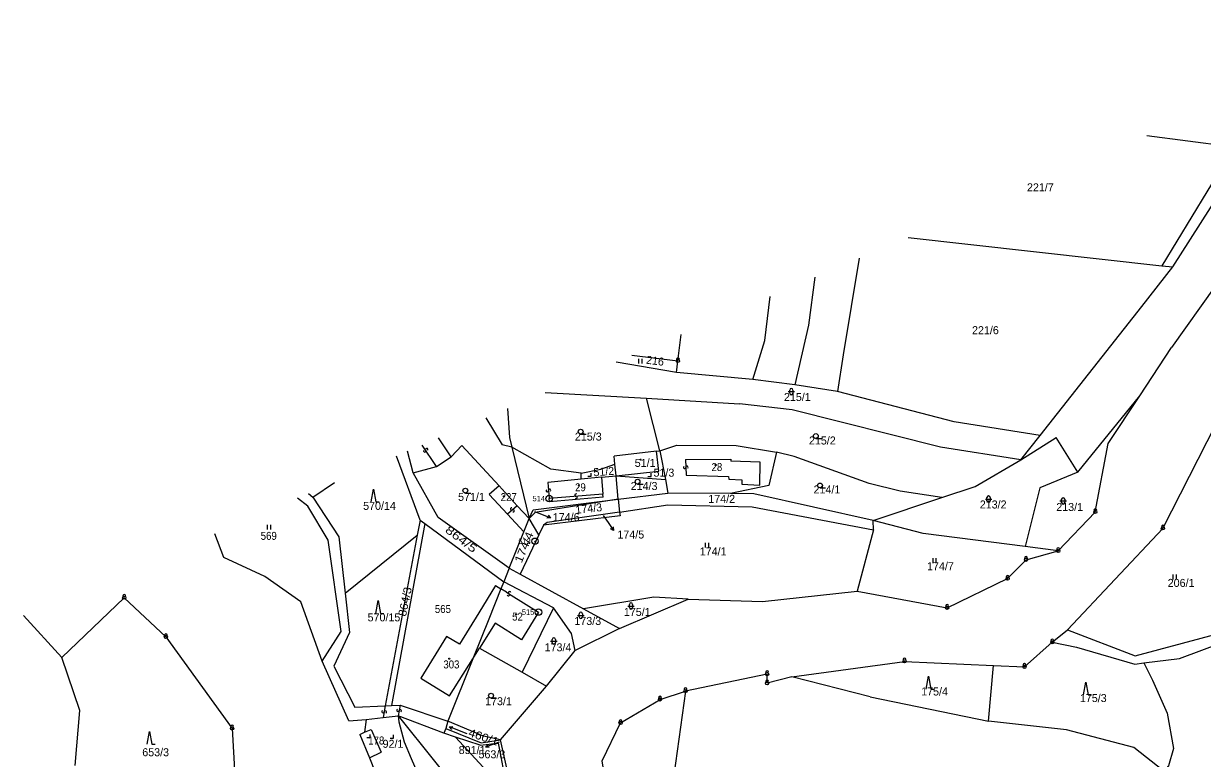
# Model space of a CAD drawing. Extents: x -680102 to -677253, y -1007548 to -1006096.
# Drawn here: x -679151.4 to -678783.2, y -1006742.4 to -1006513 of the extents above; entities that cross this region are included whole.
import ezdxf
from ezdxf.enums import TextEntityAlignment as Align

# ---------------------------------------------------------------- set-up
doc = ezdxf.new("R2010")
doc.units = 0
for name, color, linetype, lineweight in [('1', 7, 'Continuous', 25), ('13', 7, 'Continuous', 25), ('16', 7, 'Continuous', 25), ('24', 7, 'Continuous', 25), ('25', 7, 'Continuous', 25), ('4', 7, 'Continuous', 25)]:
    doc.layers.add(name, color=color, linetype=linetype, lineweight=lineweight)
for name, color, linetype in [('17', 7, 'Continuous'), ('18', 7, 'Continuous'), ('19', 7, 'Continuous')]:
    doc.layers.add(name, color=color, linetype=linetype)

msp = doc.modelspace()

# ---------------------------------------------------------------- linework, layer by layer
at = {"layer": '1'}
for p, q in [((-678800.53, -1006547.85), (-678772.56, -1006551.5)), ((-678875.09, -1006579.69), (-678795.83, -1006588.55)), ((-678890.35, -1006586.21), (-678895.4, -1006616.36)), ((-678904.28, -1006592.16), (-678906.23, -1006607.1)), ((-678906.23, -1006607.1), (-678910.46, -1006625.75)), ((-678947.49, -1006621.84), (-678966.26, -1006618.63)), ((-678895.4, -1006616.36), (-678897.14, -1006627.84)), ((-678988.49, -1006628.13), (-678956.82, -1006629.92)), ((-678822.11, -1006653.04), (-678802.77, -1006629.14)), ((-678952.68, -1006646.32), (-678956.82, -1006629.92)), ((-678956.82, -1006629.92), (-678927.82, -1006631.69)), ((-678911.3, -1006633.54), (-678927.82, -1006631.69)), ((-679006.99, -1006636.03), (-679001.94, -1006644.48)), ((-679017.85, -1006648.21), (-679021.74, -1006642.33)), ((-678998.89, -1006645.23), (-679001.94, -1006644.48)), ((-678839.88, -1006649.19), (-678828.9, -1006642.14)), ((-678822.11, -1006653.04), (-678828.9, -1006642.14)), ((-679027.56, -1006667.94), (-679034.94, -1006647.97)), ((-679029.72, -1006653.21), (-679031.49, -1006646.49)), ((-679002.88, -1006657.31), (-679014.55, -1006644.71)), ((-678986.72, -1006652.08), (-678998.89, -1006645.23)), ((-678952.68, -1006646.32), (-678947.3, -1006644.57)), ((-678916.24, -1006646.74), (-678918.62, -1006657.2)), ((-679029.72, -1006653.21), (-679022.42, -1006651.27)), ((-678971.11, -1006652.1), (-678966.67, -1006650.52)), ((-678977.27, -1006653.32), (-678971.11, -1006652.1)), ((-678970.91, -1006654.6), (-678977.24, -1006655.21)), ((-678970.91, -1006654.6), (-678966.28, -1006654.13)), ((-678966.28, -1006654.13), (-678953, -1006652.65)), ((-678965.7, -1006661.44), (-678966.28, -1006654.13)), ((-678966.28, -1006654.13), (-678950.89, -1006655.33)), ((-678822.11, -1006653.04), (-678833.99, -1006657.87)), ((-679061.04, -1006660.76), (-679054.28, -1006656.23)), ((-679002.88, -1006657.31), (-679005.93, -1006659.95)), ((-678918.62, -1006657.2), (-678930.63, -1006659.69)), ((-678864.57, -1006660.95), (-678877.56, -1006658.92)), ((-678833.99, -1006657.87), (-678838.55, -1006676.25)), ((-679062.63, -1006663.61), (-679065.81, -1006661.15)), ((-679062.41, -1006659.7), (-679061.04, -1006660.76)), ((-679061.04, -1006660.76), (-679052.88, -1006673.15)), ((-679000.23, -1006666.1), (-679005.93, -1006659.95)), ((-678965.7, -1006661.44), (-678991.57, -1006665.59)), ((-678965.7, -1006661.44), (-678950.19, -1006659.59)), ((-679056.21, -1006674.25), (-679062.63, -1006663.61)), ((-678995.13, -1006671.61), (-679000.23, -1006666.1)), ((-678991.57, -1006665.59), (-678993.47, -1006667.47)), ((-678965.21, -1006665.45), (-678950.17, -1006663.23)), ((-679026.09, -1006669.03), (-679036.42, -1006725.89)), ((-678990.43, -1006672.51), (-678993.47, -1006667.47)), ((-678965.06, -1006666.67), (-678989.01, -1006669.52)), ((-678870.38, -1006672.11), (-678885.98, -1006668.07)), ((-679050.96, -1006690.78), (-679028.44, -1006672.66)), ((-678885.94, -1006671.03), (-678890.99, -1006690.13)), ((-679003.94, -1006688.36), (-679002.28, -1006689.39)), ((-679139.41, -1006710.89), (-679119.95, -1006692.18)), ((-678954.49, -1006692.05), (-678976.49, -1006695.68)), ((-678985.89, -1006695.35), (-678995.64, -1006715.45)), ((-678976.49, -1006695.68), (-678965.27, -1006701.83)), ((-679151.39, -1006697.71), (-679139.41, -1006710.89)), ((-678965.27, -1006701.83), (-678979.06, -1006708.64)), ((-679011.06, -1006711.25), (-679008.94, -1006707.89)), ((-679133.78, -1006727.4), (-679139.41, -1006710.89)), ((-679018.38, -1006722.85), (-679011.06, -1006711.25)), ((-678911.38, -1006716.94), (-678876.22, -1006712.06)), ((-678849.98, -1006730.68), (-678848.47, -1006713.33)), ((-678886.94, -1006723.16), (-678911.38, -1006716.94)), ((-679002.4, -1006736.58), (-678988.1, -1006719.85)), ((-678886.94, -1006723.16), (-678849.98, -1006730.68)), ((-679135.24, -1006744.53), (-679133.78, -1006727.4)), ((-679047.91, -1006726.37), (-679038.41, -1006725.97)), ((-679033.77, -1006725.78), (-679018.9, -1006730.77)), ((-679046.38, -1006734.91), (-679044.89, -1006734.19)), ((-679046.38, -1006734.91), (-679043.31, -1006742.18)), ((-679044.89, -1006734.19), (-679042.83, -1006733.34)), ((-679042.83, -1006733.34), (-679039.71, -1006740.37)), ((-679019.52, -1006733.05), (-679020.07, -1006734.51)), ((-679005.39, -1006747.73), (-679016.43, -1006735.68)), ((-679043.31, -1006742.18), (-679039.71, -1006740.37)), ((-679043.31, -1006742.18), (-679035.43, -1006762.21)), ((-679002.29, -1006741.89), (-679001.73, -1006745.16))]:
    msp.add_line(p, q, dxfattribs=at)
for points in [[(-678718.85, -1006512.96), (-678727.87, -1006520.67), (-678750.9, -1006553.44), (-678779.15, -1006594.96), (-678792.87, -1006614.12)], [(-678833.83, -1006641.55), (-678802.15, -1006601.31), (-678792.37, -1006588.89), (-678778.26, -1006566.69), (-678751.77, -1006529.49), (-678748.59, -1006525.66)], [(-678777.09, -1006557.74), (-678795.83, -1006588.55), (-678792.37, -1006588.89)], [(-678923.64, -1006624.05), (-678919.88, -1006611.91), (-678918.24, -1006598.12)], [(-678828.22, -1006677.6), (-678816.63, -1006665.45), (-678812.58, -1006644.03), (-678802.77, -1006629.14), (-678792.87, -1006614.12)], [(-678839.88, -1006649.19), (-678833.83, -1006641.55), (-678860.72, -1006637.24), (-678897.14, -1006627.84), (-678910.46, -1006625.75), (-678923.64, -1006624.05), (-678947.49, -1006621.84), (-678946.99, -1006618.31)], [(-678825.3, -1006702.25), (-678795.52, -1006670.55), (-678770.69, -1006621.83), (-678771.83, -1006639.32), (-678780, -1006672.18), (-678768.75, -1006700.87)], [(-678854.19, -1006657.49), (-678839.88, -1006649.19), (-678865.03, -1006645.21), (-678911.3, -1006633.54)], [(-679022.42, -1006651.27), (-679017.85, -1006648.21), (-679014.55, -1006644.71)], [(-678953, -1006652.65), (-678953.69, -1006646.44), (-678966.94, -1006647.96)], [(-678966.28, -1006654.13), (-678966.67, -1006650.52), (-678966.94, -1006647.96)], [(-678953.69, -1006646.44), (-678952.68, -1006646.32), (-678950.89, -1006655.33), (-678950.19, -1006659.59)], [(-678947.3, -1006644.57), (-678928.77, -1006644.65), (-678916.24, -1006646.74)], [(-678877.56, -1006658.92), (-678887.22, -1006656.57), (-678910.72, -1006648.08), (-678916.24, -1006646.74)], [(-678999.7, -1006682.97), (-679021.88, -1006667.12), (-679029.72, -1006653.21)], [(-678977.24, -1006655.21), (-678977.27, -1006653.32), (-678986.72, -1006652.08)], [(-678993.47, -1006667.47), (-678997.18, -1006663.47), (-679002.88, -1006657.31)], [(-678885.98, -1006668.07), (-678864.57, -1006660.95), (-678854.19, -1006657.49)], [(-678993.47, -1006667.47), (-678992.27, -1006664.73), (-678965.7, -1006661.44)], [(-678965.7, -1006661.44), (-678965.21, -1006665.45), (-678965.06, -1006666.67)], [(-678923.28, -1006659.73), (-678930.63, -1006659.69), (-678950.19, -1006659.59)], [(-678885.94, -1006671.03), (-678885.98, -1006668.07), (-678923.28, -1006659.73)], [(-678965.21, -1006665.45), (-678987.83, -1006668.67), (-678989.01, -1006669.52)], [(-678950.17, -1006663.23), (-678923.81, -1006663.85), (-678885.94, -1006671.03)], [(-679027.56, -1006667.94), (-679028.44, -1006672.66), (-679038.41, -1006725.97)], [(-679027.56, -1006667.94), (-679026.09, -1006669.03), (-679001.42, -1006687.25)], [(-678989.01, -1006669.52), (-678990.43, -1006672.51), (-678996.3, -1006684.83)], [(-679049.77, -1006730.67), (-679058.14, -1006711.95), (-679064.82, -1006693.49), (-679076.06, -1006685.58), (-679088.89, -1006679.61), (-679091.68, -1006672.2)], [(-679052.88, -1006673.15), (-679050.96, -1006690.78), (-679049.63, -1006703.03)], [(-678828.22, -1006677.6), (-678838.55, -1006676.25), (-678870.38, -1006672.11)], [(-679058.14, -1006711.95), (-679052.24, -1006702.77), (-679056.21, -1006674.25)], [(-678943.78, -1006692.62), (-678920.62, -1006693.39), (-678890.99, -1006690.13), (-678862.92, -1006695.35), (-678844.01, -1006686.22), (-678838.27, -1006680.34), (-678828.22, -1006677.6)], [(-678999.7, -1006682.97), (-678996.3, -1006684.83), (-678976.49, -1006695.68)], [(-679003.94, -1006688.36), (-679009.2, -1006696.89), (-679015.28, -1006706.74), (-679019.25, -1006704.29), (-679027.31, -1006717.34), (-679018.38, -1006722.85)], [(-678980.21, -1006703.33), (-678985.89, -1006695.35), (-679001.42, -1006687.25)], [(-679119.95, -1006692.18), (-679106.93, -1006704.42), (-679086.25, -1006732.99)], [(-678965.27, -1006701.83), (-678943.78, -1006692.62), (-678954.49, -1006692.05)], [(-678830.07, -1006706.12), (-678825.3, -1006702.25), (-678804.17, -1006710.32), (-678768.75, -1006700.87), (-678759.35, -1006690.53)], [(-679049.63, -1006703.03), (-679054.45, -1006713.53), (-679047.91, -1006726.37)], [(-678988.1, -1006719.85), (-678979.06, -1006708.64), (-678980.21, -1006703.33)], [(-678801.5, -1006712.47), (-678790.35, -1006711.15), (-678764.08, -1006701.41)], [(-678838.75, -1006713.78), (-678830.07, -1006706.12), (-678822.48, -1006707.68), (-678804.29, -1006712.9), (-678801.5, -1006712.47), (-678798.75, -1006717.89)], [(-679008.94, -1006707.89), (-678995.64, -1006715.45), (-678988.1, -1006719.85)], [(-678876.22, -1006712.06), (-678848.47, -1006713.33), (-678838.75, -1006713.78)], [(-678911.38, -1006716.94), (-678919.14, -1006718.89), (-678919.14, -1006716.04), (-678944.63, -1006721.34)], [(-678798.75, -1006717.89), (-678794.19, -1006728.21), (-678792.25, -1006739.23), (-678793.8, -1006744.67), (-678795.23, -1006746.35), (-678804.55, -1006738.97), (-678825.66, -1006733.4), (-678849.98, -1006730.68)], [(-678972.03, -1006782.95), (-678974.11, -1006769.23), (-678969.55, -1006750.45), (-678970.65, -1006743.09), (-678964.92, -1006731.27), (-678952.59, -1006723.96), (-678944.63, -1006721.34)], [(-678944.63, -1006721.34), (-678954, -1006788.76), (-678925.55, -1006782.25), (-678911.96, -1006785.6), (-678905.55, -1006793.77), (-678908.87, -1006800.86), (-678918.43, -1006806.7), (-678921.1, -1006820.24)], [(-679044.33, -1006730.22), (-679039.1, -1006729.63), (-679034.41, -1006729.1)], [(-679038.41, -1006725.97), (-679036.42, -1006725.89), (-679033.77, -1006725.78)], [(-679020.07, -1006734.51), (-679034.41, -1006729.1), (-679011.73, -1006757.42)], [(-679034.41, -1006729.1), (-679034.2, -1006730.94), (-679032.56, -1006737.17)], [(-679049.77, -1006730.67), (-679044.33, -1006730.22), (-679044.89, -1006734.19)], [(-679002.4, -1006736.58), (-679007.76, -1006735.45), (-679018.9, -1006730.77)], [(-679086.25, -1006732.99), (-679084.6, -1006762.61), (-679086.42, -1006772.41)], [(-679008.78, -1006738.21), (-679016.43, -1006735.68), (-679020.07, -1006734.51)], [(-679032.56, -1006737.17), (-679030.31, -1006742.36), (-679023.46, -1006758.19)], [(-679008.78, -1006738.21), (-679003.18, -1006737.62), (-679002.29, -1006741.89)]]:
    msp.add_lwpolyline(points, dxfattribs=at)
at = {"layer": '13'}
for p, q in [((-678946.99, -1006618.31), (-678946, -1006609.98)), ((-678946.99, -1006618.31), (-678961.4, -1006616.56)), ((-679000.24, -1006633.15), (-678999.62, -1006642.21)), ((-678999.62, -1006642.21), (-678998.89, -1006645.23)), ((-678998.89, -1006645.23), (-678993.47, -1006667.47)), ((-678999.7, -1006682.97), (-679001.42, -1006687.25))]:
    msp.add_line(p, q, dxfattribs=at)
for points in [[(-678999.7, -1006682.97), (-678995.13, -1006671.61), (-678993.47, -1006667.47)], [(-679001.42, -1006687.25), (-679002.28, -1006689.39), (-679006.1, -1006698.89), (-679011.06, -1006711.25)], [(-679011.06, -1006711.25), (-679018.9, -1006730.77), (-679019.52, -1006733.05), (-679008.5, -1006737.54), (-679002.4, -1006736.58)], [(-679000.37, -1006745.89), (-679000.69, -1006744.42), (-679002.4, -1006736.58)]]:
    msp.add_lwpolyline(points, dxfattribs=at)
at = {"layer": '16'}
for p, q in [((-678991.82, -1006665.25), (-678989.59, -1006666.15)), ((-678989.59, -1006666.15), (-678986.813, -1006667.283)), ((-678970.35, -1006666.54), (-678968.81, -1006668.75)), ((-678968.81, -1006668.75), (-678967.098, -1006671.213)), ((-679004.25, -1006737.82), (-679007.069, -1006738.846)), ((-679002.8, -1006737.29), (-679004.25, -1006737.82))]:
    msp.add_line(p, q, dxfattribs=at)
for points in [[(-678987.55, -1006666.442), (-678986.813, -1006667.283), (-678987.928, -1006667.368)], [(-678967.258, -1006670.106), (-678967.098, -1006671.213), (-678968.08, -1006670.677)], [(-679005.958, -1006738.973), (-679007.069, -1006738.846), (-679006.3, -1006738.034)]]:
    msp.add_lwpolyline(points, dxfattribs=at)
at = {"layer": '24'}
for centre, radius in [((-678946.99, -1006618.31), 0.5), ((-678946.99, -1006618.31), 0.022), ((-678987.23, -1006661.25), 1), ((-678987.23, -1006661.25), 0.032), ((-678816.63, -1006665.45), 0.5), ((-678816.63, -1006665.45), 0.022), ((-678795.52, -1006670.55), 0.5), ((-678991.66, -1006674.56), 1), ((-678795.52, -1006670.55), 0.022), ((-678991.66, -1006674.56), 0.032), ((-678828.22, -1006677.6), 0.5), ((-678828.22, -1006677.6), 0.022), ((-678838.27, -1006680.34), 0.5), ((-678838.27, -1006680.34), 0.022), ((-678844.01, -1006686.22), 0.5), ((-678844.01, -1006686.22), 0.022), ((-679119.95, -1006692.18), 0.5), ((-679119.95, -1006692.18), 0.022), ((-678990.55, -1006696.69), 1), ((-678862.92, -1006695.35), 0.5), ((-678862.92, -1006695.35), 0.022), ((-678990.55, -1006696.69), 0.032), ((-679106.93, -1006704.42), 0.5), ((-679106.93, -1006704.42), 0.022), ((-678830.07, -1006706.12), 0.5), ((-678830.07, -1006706.12), 0.022), ((-678876.22, -1006712.06), 0.5), ((-678876.22, -1006712.06), 0.022), ((-678838.75, -1006713.78), 0.5), ((-678838.75, -1006713.78), 0.022), ((-678919.14, -1006716.04), 0.5), ((-678919.14, -1006716.04), 0.022), ((-678944.63, -1006721.34), 0.5), ((-678944.63, -1006721.34), 0.022), ((-678919.14, -1006718.89), 0.5), ((-678919.14, -1006718.89), 0.022), ((-678952.59, -1006723.96), 0.5), ((-678952.59, -1006723.96), 0.022), ((-679086.25, -1006732.99), 0.5), ((-678964.92, -1006731.27), 0.5), ((-678964.92, -1006731.27), 0.022), ((-679086.25, -1006732.99), 0.022)]:
    msp.add_circle(centre, radius, dxfattribs=at)
for centre in [(-678946.991, -1006617.747), (-678816.631, -1006664.887), (-678795.521, -1006669.987), (-678828.221, -1006677.037), (-678838.271, -1006679.777), (-678844.011, -1006685.657), (-679119.951, -1006691.617), (-678862.921, -1006694.787), (-679106.931, -1006703.857), (-678830.071, -1006705.557), (-678876.221, -1006711.497), (-678838.751, -1006713.217), (-678919.141, -1006715.477), (-678919.141, -1006718.327), (-678944.631, -1006720.777), (-678952.591, -1006723.397), (-679086.251, -1006732.427), (-678964.921, -1006730.707)]:
    msp.add_arc(centre, 0.437, 328.35109, 209.97456, dxfattribs=at)
at = {"layer": '25'}
for p, q in [((-678959.187, -1006619.095), (-678959.187, -1006617.595)), ((-678958.153, -1006619.095), (-678958.153, -1006617.595)), ((-678912.56, -1006627.86), (-678910.56, -1006627.86)), ((-678912.06, -1006628.36), (-678912.06, -1006627.36)), ((-678911.06, -1006627.36), (-678911.06, -1006628.36)), ((-678977.4, -1006641.09), (-678975.65, -1006641.09)), ((-678903.93, -1006642.47), (-678902.18, -1006642.47)), ((-678959.6, -1006656.71), (-678957.85, -1006656.71)), ((-678902.62, -1006657.88), (-678900.87, -1006657.88)), ((-679013.4, -1006659.51), (-679011.65, -1006659.51)), ((-678850.97, -1006661.41), (-678848.97, -1006661.41)), ((-678850.47, -1006661.91), (-678850.47, -1006660.91)), ((-678849.47, -1006660.91), (-678849.47, -1006661.91)), ((-678827.68, -1006661.96), (-678825.68, -1006661.96)), ((-678827.18, -1006662.46), (-678827.18, -1006661.46)), ((-678826.18, -1006661.46), (-678826.18, -1006662.46)), ((-679075.177, -1006670.935), (-679075.177, -1006669.435)), ((-679074.143, -1006670.935), (-679074.143, -1006669.435)), ((-678938.397, -1006676.565), (-678938.397, -1006675.065)), ((-678937.363, -1006676.565), (-678937.363, -1006675.065)), ((-678867.327, -1006681.355), (-678867.327, -1006679.855)), ((-678866.293, -1006681.355), (-678866.293, -1006679.855)), ((-678792.287, -1006686.495), (-678792.287, -1006684.995)), ((-678791.253, -1006686.495), (-678791.253, -1006684.995)), ((-678962.68, -1006694.79), (-678960.68, -1006694.79)), ((-678962.18, -1006695.29), (-678962.18, -1006694.29)), ((-678961.18, -1006694.29), (-678961.18, -1006695.29)), ((-678978.32, -1006697.71), (-678976.32, -1006697.71)), ((-678977.82, -1006698.21), (-678977.82, -1006697.21)), ((-678976.82, -1006697.21), (-678976.82, -1006698.21)), ((-678986.76, -1006705.71), (-678984.76, -1006705.71)), ((-678986.26, -1006706.21), (-678986.26, -1006705.21)), ((-678985.26, -1006705.21), (-678985.26, -1006706.21)), ((-679005.37, -1006723.52), (-679003.62, -1006723.52)), ((-679012.809, -1006734.649), (-679018.391, -1006732.451))]:
    msp.add_line(p, q, dxfattribs=at)
for points in [[(-678975.12, -1006654.26), (-678974.12, -1006654.26), (-678974.12, -1006653.26)], [(-678956.35, -1006654.34), (-678955.35, -1006654.34), (-678955.35, -1006653.34)], [(-679042.82, -1006662.26), (-679042.07, -1006658.26), (-679041.32, -1006662.26), (-679040.32, -1006662.26)], [(-679041.39, -1006697.07), (-679040.64, -1006693.07), (-679039.89, -1006697.07), (-679038.89, -1006697.07)], [(-678869.51, -1006720.7), (-678868.76, -1006716.7), (-678868.01, -1006720.7), (-678867.01, -1006720.7)], [(-678820.33, -1006722.51), (-678819.58, -1006718.51), (-678818.83, -1006722.51), (-678817.83, -1006722.51)], [(-679017.644, -1006733.283), (-679018.391, -1006732.451), (-679017.277, -1006732.352)], [(-679112.83, -1006737.96), (-679112.08, -1006733.96), (-679111.33, -1006737.96), (-679110.33, -1006737.96)], [(-679044.15, -1006735.87), (-679043.15, -1006735.87), (-679043.15, -1006734.87)], [(-679036.89, -1006736.04), (-679035.89, -1006736.04), (-679035.89, -1006735.04)]]:
    msp.add_lwpolyline(points, dxfattribs=at)
for centre, radius in [((-678977.4, -1006640.34), 0.75), ((-678903.93, -1006641.72), 0.75), ((-678958.66, -1006649.07), 0.175), ((-678935.21, -1006650.75), 0.175), ((-678959.6, -1006655.96), 0.75), ((-679013.4, -1006658.76), 0.75), ((-678977.95, -1006657.14), 0.175), ((-678902.62, -1006657.13), 0.75), ((-679001.35, -1006660.53), 0.175), ((-678997.52, -1006697.39), 0.175), ((-679018.43, -1006711.22), 0.175), ((-679005.37, -1006722.77), 0.75)]:
    msp.add_circle(centre, radius, dxfattribs=at)
for centre, radius, start, end in [((-678911.56, -1006627.36), 0.5, 0.101, 180.00143), ((-678911.56, -1006628.36), 0.5, 180.10243, 0.00286), ((-679026.079, -1006646.369), 0.368, 160.77459, 32.78232), ((-679025.46, -1006645.971), 0.369, 340.53684, 212.67043), ((-678944.928, -1006651.522), 0.368, 130.04559, 1.87055), ((-678944.193, -1006651.496), 0.367, 309.80156, 182.18606), ((-678987.807, -1006658.751), 0.368, 132.9125, 4.57004), ((-678987.074, -1006658.688), 0.368, 312.54089, 184.99823), ((-678978.866, -1006660.143), 0.368, 42.03373, 273.9), ((-678978.813, -1006660.876), 0.367, 221.91916, 94.21984), ((-678849.97, -1006660.91), 0.5, 0.101, 180.00143), ((-678849.97, -1006661.91), 0.5, 180.10243, 0.00286), ((-678826.68, -1006661.46), 0.5, 0.101, 180.00143), ((-678826.68, -1006662.46), 0.5, 180.10243, 0.00286), ((-678998.937, -1006664.508), 0.369, 77.96007, 309.97962), ((-678998.463, -1006665.071), 0.368, 257.61382, 130.14587), ((-679000, -1006691.25), 0.369, 184.98469, 57.08024), ((-678999.602, -1006690.63), 0.368, 5.1383, 237.43512), ((-678961.68, -1006694.29), 0.5, 0.101, 180.00143), ((-678961.68, -1006695.29), 0.5, 180.10243, 0.00286), ((-678977.32, -1006697.21), 0.5, 0.101, 180.00143), ((-678977.32, -1006698.21), 0.5, 180.10243, 0.00286), ((-678985.76, -1006705.21), 0.5, 0.101, 180.00143), ((-678985.76, -1006706.21), 0.5, 180.10243, 0.00286), ((-679039.121, -1006727.728), 0.368, 116.77458, 348.72337), ((-679038.399, -1006727.87), 0.367, 296.43668, 169.02754), ((-679034.451, -1006727.366), 0.368, 116.42691, 348.4184), ((-679033.73, -1006727.513), 0.367, 295.99051, 168.53846)]:
    msp.add_arc(centre, radius, start, end, dxfattribs=at)
at = {"layer": '4'}
for p, q in [((-679022.42, -1006651.27), (-679026.86, -1006644.52)), ((-678977.24, -1006655.21), (-678987.68, -1006656.24)), ((-678970.91, -1006654.6), (-678970.48, -1006659.82)), ((-678987.68, -1006656.24), (-678987.21, -1006661.19)), ((-678970.48, -1006659.82), (-678987.21, -1006661.19)), ((-678987.11, -1006662.22), (-678987.21, -1006661.19)), ((-678970.4, -1006660.82), (-678987.11, -1006662.22)), ((-678970.4, -1006660.82), (-678970.48, -1006659.82)), ((-678997.18, -1006663.47), (-679000.23, -1006666.1)), ((-679000.54, -1006690.47), (-679002.28, -1006689.39)), ((-679004.08, -1006700.18), (-679008.94, -1006707.89)), ((-678995.86, -1006705.29), (-679004.08, -1006700.18)), ((-679038.41, -1006725.97), (-679039.1, -1006729.63)), ((-679033.77, -1006725.78), (-679034.41, -1006729.1))]:
    msp.add_line(p, q, dxfattribs=at)
for points in [[(-678944.67, -1006649.04), (-678930.51, -1006648.99), (-678930.51, -1006649.55)], [(-678944.67, -1006649.04), (-678944.45, -1006653.97), (-678931.18, -1006654.32), (-678931.11, -1006655.18), (-678927.04, -1006655.38), (-678927.04, -1006656.7), (-678921.39, -1006657.04)], [(-678921.39, -1006657.04), (-678921.27, -1006649.88), (-678930.51, -1006649.55)], [(-679000.54, -1006690.47), (-678999.06, -1006691.4), (-678990.54, -1006696.73), (-678995.86, -1006705.29)]]:
    msp.add_lwpolyline(points, dxfattribs=at)

# ---------------------------------------------------------------- texts
at = {"layer": '16'}
for s, p in [('174/6', (-678986.09, -1006668.29)), ('174/5', (-678965.9, -1006673.71))]:
    msp.add_text(s, height=2.5, dxfattribs=at).set_placement(p)
msp.add_text('891/1', height=2.5, dxfattribs=at).set_placement((-679007.11, -1006741), align=Align.RIGHT)
at = {"layer": '17', "width": 0.9}
for s, p in [('514', (-678988.53, -1006662.1)), ('513', (-678992.96, -1006675.41)), ('515', (-678991.85, -1006697.54))]:
    msp.add_text(s, height=1.7, dxfattribs=at).set_placement(p, align=Align.RIGHT)
at = {"layer": '18'}
for s, height, p in [('221/7', 2.5, (-678837.98, -1006565.33)), ('221/6', 2.5, (-678855.14, -1006609.92)), ('215/1', 2.5, (-678913.89, -1006630.78)), ('215/3', 2.5, (-678979.18, -1006643.13)), ('215/2', 2.5, (-678906.08, -1006644.36)), ('214/3', 2.5, (-678961.75, -1006658.57)), ('214/1', 2.5, (-678904.64, -1006659.64)), ('570/14', 2.5, (-679045.33, -1006664.76)), ('571/1', 2.5, (-679015.67, -1006661.95)), ('174/2', 2.5, (-678937.51, -1006662.58)), ('213/2', 2.5, (-678852.72, -1006664.33)), ('213/1', 2.5, (-678828.83, -1006665.12)), ('174/6', 0.1, (-678991.62, -1006665.05)), ('174/5', 0.1, (-678970.15, -1006666.34)), ('174/1', 2.5, (-678940.18, -1006678.99)), ('174/7', 2.5, (-678869.19, -1006683.61)), ('206/1', 2.5, (-678794.02, -1006688.82)), ('175/1', 2.5, (-678963.89, -1006697.88)), ('570/15', 2.5, (-679043.94, -1006699.57)), ('173/3', 2.5, (-678979.35, -1006700.69)), ('173/4', 2.5, (-678988.64, -1006708.93)), ('175/4', 2.5, (-678871.02, -1006722.71)), ('173/1', 2.5, (-679007.24, -1006725.76)), ('175/3', 2.5, (-678821.45, -1006724.77)), ('653/3', 2.5, (-679114.32, -1006741.68)), ('563/3', 2.5, (-679009.29, -1006742.32))]:
    msp.add_text(s, height=height, dxfattribs=at).set_placement(p)
for s, rotation, p in [('216', 352.903, (-678957.057, -1006619.117)), ('174/3', 6, (-678978.893, -1006666.011))]:
    msp.add_text(s, height=2.5, rotation=rotation, dxfattribs=at).set_placement(p)
for s, rotation, width, p in [('864/5', 322.903, 1.35, (-679019.95, -1006671.512)), ('174/4', 67.601, 1.2, (-678995.838, -1006681.559)), ('864/3', 78.201, 1.1, (-679031.974, -1006698.174)), ('460/1', 341.303, 1.15, (-679012.677, -1006735.345))]:
    msp.add_text(s, height=2.5, rotation=rotation, dxfattribs=dict(at, width=width)).set_placement(p)
at = {"layer": '18', "width": 0.9}
msp.add_text('569', height=2.5, dxfattribs=at).set_placement((-679074.809, -1006674.13), align=Align.CENTER)
msp.add_text('565', height=2.5, dxfattribs=at).set_placement((-679022.92, -1006696.96))
at = {"layer": '18'}
msp.add_text('891/1', height=0.1, dxfattribs=at).set_placement((-679002.6, -1006737.09), align=Align.CENTER)
at = {"layer": '19'}
msp.add_text('51/2', height=2.5, rotation=4.5, dxfattribs=at).set_placement((-678973.317, -1006654.305))
for s, p in [('51/1', (-678960.5, -1006651.36)), ('51/3', (-678954.63, -1006654.4))]:
    msp.add_text(s, height=2.5, dxfattribs=at).set_placement(p)
at = {"layer": '19', "width": 0.9}
for s, p in [('28', (-678936.5, -1006652.65)), ('29', (-678979.13, -1006658.96)), ('227', (-679002.37, -1006662.04)), ('52', (-678998.78, -1006699.34)), ('303', (-679020.27, -1006714.27)), ('178', (-679043.74, -1006738.02))]:
    msp.add_text(s, height=2.5, dxfattribs=at).set_placement(p)
at = {"layer": '19'}
msp.add_text('92/1', height=2.5, dxfattribs=at).set_placement((-679036, -1006739.04), align=Align.CENTER)

doc.saveas('drawing.dxf')
